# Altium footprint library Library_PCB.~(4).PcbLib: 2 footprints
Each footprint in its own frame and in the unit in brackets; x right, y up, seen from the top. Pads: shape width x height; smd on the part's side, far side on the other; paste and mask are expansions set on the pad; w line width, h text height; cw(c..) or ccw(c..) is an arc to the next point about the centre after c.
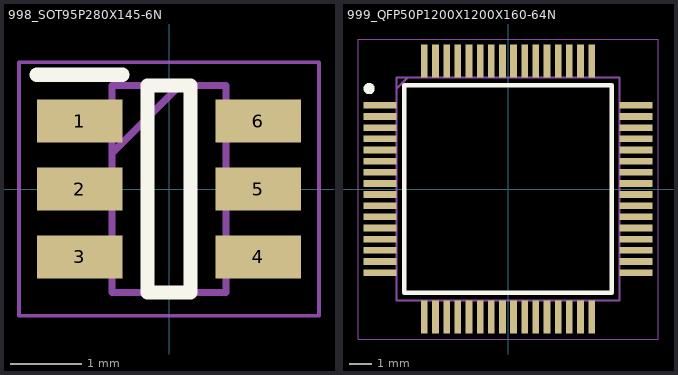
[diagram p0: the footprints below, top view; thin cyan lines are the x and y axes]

## 998_SOT95P280X145-6N [mm]
pads (6):
  rect 1.2x0.6 smd: 1(-1.25,0.95) 2(-1.25,0) 3(-1.25,-0.95) 4(1.25,-0.95) 5(1.25,0) 6(1.25,0.95)
Top Overlay:
  lines w0.2: -1.85,1.6 -0.65,1.6 ; -0.3,-1.45 -0.3,1.45 0.3,1.45 0.3,-1.45 -0.3,-1.45
Mechanical 15:
  lines w0.1: -0.8,0.5 0.15,1.45 ; -0.8,-1.45 -0.8,1.45 0.8,1.45 0.8,-1.45 -0.8,-1.45
Mechanical 20:
  lines w0.05: -2.1,-1.775 -2.1,1.775 2.1,1.775 2.1,-1.775 -2.1,-1.775
3D body "TPS560430X3FDBVR.stp": height 1.45, standoff 0, extent -1.4,-1.45 1.4,1.45

## 999_QFP50P1200X1200X160-64N [mm]
pads (64):
  rect 1.475x0.3 smd: 1(-5.738,3.75) 2(-5.738,3.25) 3(-5.738,2.75) 4(-5.738,2.25) 5(-5.738,1.75) 6(-5.738,1.25) 7(-5.738,0.75) 8(-5.738,0.25) 9(-5.738,-0.25) 10(-5.738,-0.75) 11(-5.738,-1.25) 12(-5.738,-1.75) 13(-5.738,-2.25) 14(-5.738,-2.75) 15(-5.738,-3.25) 16(-5.738,-3.75) 33(5.738,-3.75) 34(5.738,-3.25) 35(5.738,-2.75) 36(5.738,-2.25) 37(5.738,-1.75) 38(5.738,-1.25) 39(5.738,-0.75) 40(5.738,-0.25) 41(5.738,0.25) 42(5.738,0.75) 43(5.738,1.25) 44(5.738,1.75) 45(5.738,2.25) 46(5.738,2.75) 47(5.738,3.25) 48(5.738,3.75)
  rect 0.3x1.475 smd: 17(-3.75,-5.738) 18(-3.25,-5.738) 19(-2.75,-5.738) 20(-2.25,-5.738) 21(-1.75,-5.738) 22(-1.25,-5.738) 23(-0.75,-5.738) 24(-0.25,-5.738) 25(0.25,-5.738) 26(0.75,-5.738) 27(1.25,-5.738) 28(1.75,-5.738) 29(2.25,-5.738) 30(2.75,-5.738) 31(3.25,-5.738) 32(3.75,-5.738) 49(3.75,5.738) 50(3.25,5.738) 51(2.75,5.738) 52(2.25,5.738) 53(1.75,5.738) 54(1.25,5.738) 55(0.75,5.738) 56(0.25,5.738) 57(-0.25,5.738) 58(-0.75,5.738) 59(-1.25,5.738) 60(-1.75,5.738) 61(-2.25,5.738) 62(-2.75,5.738) 63(-3.25,5.738) 64(-3.75,5.738)
Top Overlay:
  circle w0.25: c-6.225,4.5 r0.125
  lines w0.2: -4.65,-4.65 -4.65,4.65 4.65,4.65 4.65,-4.65 -4.65,-4.65
Mechanical 15:
  lines w0.1: -5,4.5 -4.5,5 ; -5,-5 -5,5 5,5 5,-5 -5,-5
Mechanical 20:
  lines w0.05: -6.725,-6.725 -6.725,6.725 6.725,6.725 6.725,-6.725 -6.725,-6.725
3D body "STM32G431RBT6.stp": height 1.6, standoff 0, extent -6,-6 6,6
